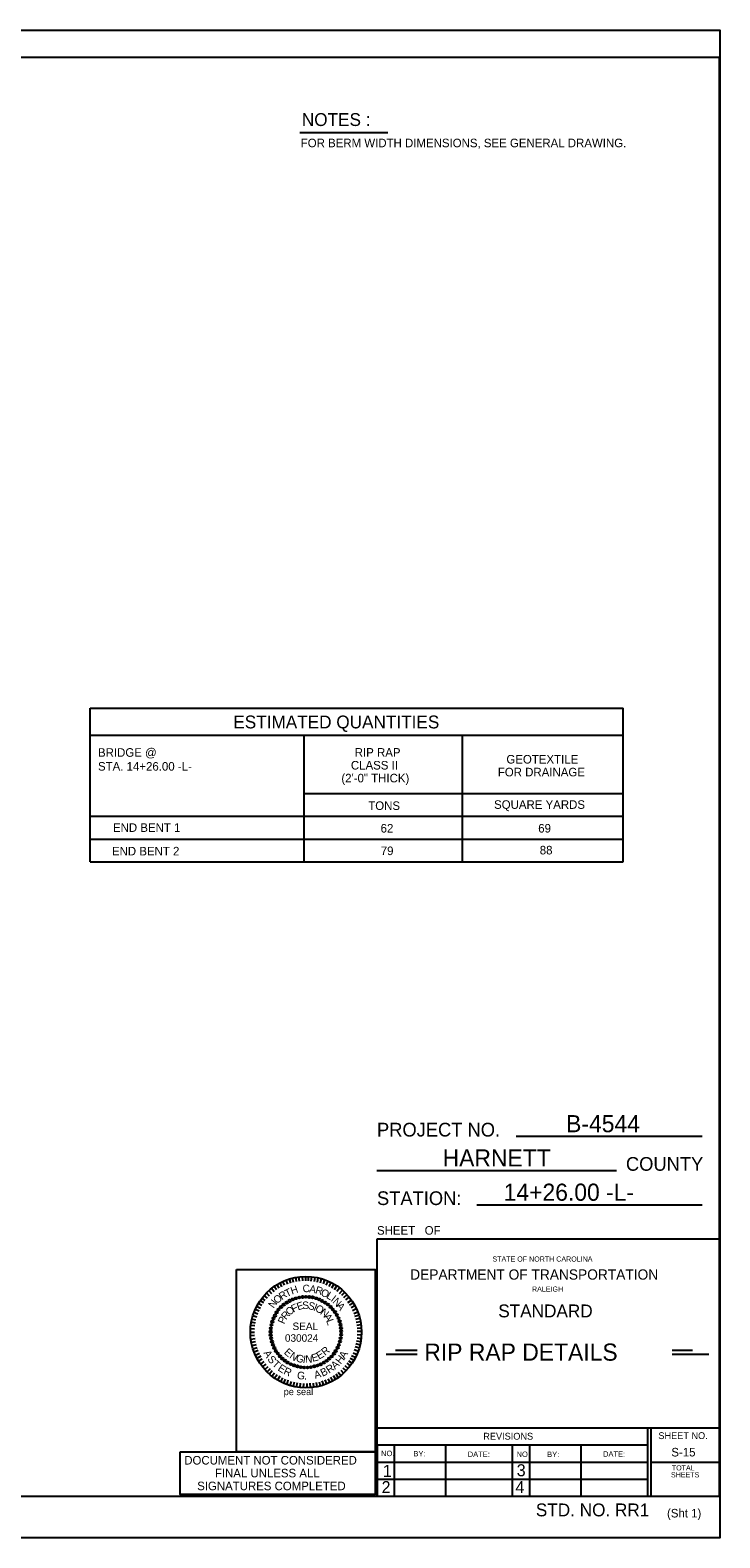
# Model space of a CAD drawing. Extents: x -102 to 265, y 0 to 198.
# Drawn here: x 183.9 to 264.5, y 0 to 176 of the extents above; entities that cross this region are included whole.
import ezdxf

# ---------------------------------------------------------------- set-up
doc = ezdxf.new("R2010")
doc.units = 0
for name, color, linetype in [('Peseal', 7, 'Continuous'), ('Plan Sheet', 7, 'Continuous'), ('Plan Sheet CELL', 7, 'Continuous'), ('Plot Shape', 7, 'Continuous'), ('Sheet Sticker Exception Certification CELL', 7, 'Continuous'), ('Text', 7, 'Continuous'), ('Title Text', 7, 'Continuous'), ('User Information Notes', 7, 'Continuous'), ('User Information Notes CELL', 7, 'Continuous')]:
    doc.layers.add(name, color=color, linetype=linetype)

msp = doc.modelspace()

# ---------------------------------------------------------------- linework, layer by layer
at = {"layer": 'Peseal'}
for p, q in [((214.01, 29.61), (213.82, 30.07)), ((214.36, 29.73), (214.2, 30.23)), ((214.7, 29.82), (214.57, 30.32)), ((215.04, 29.92), (214.95, 30.42)), ((215.39, 29.95), (215.32, 30.45)), ((215.76, 30.01), (215.73, 30.51)), ((216.14, 30.01), (216.14, 30.51)), ((216.42, 30.01), (216.45, 30.51)), ((216.76, 29.98), (216.82, 30.48)), ((217.14, 29.92), (217.2, 30.42)), ((217.48, 29.86), (217.57, 30.36)), ((217.82, 29.76), (217.95, 30.26)), ((218.17, 29.67), (218.36, 30.14)), ((218.51, 29.51), (218.73, 29.98)), ((211.64, 27.98), (211.26, 28.29)), ((211.89, 28.23), (211.51, 28.61)), ((212.14, 28.48), (211.82, 28.86)), ((212.42, 28.73), (212.11, 29.11)), ((212.7, 28.95), (212.42, 29.36)), ((213.01, 29.14), (212.76, 29.57)), ((213.32, 29.32), (213.11, 29.76)), ((213.64, 29.48), (213.45, 29.92)), ((218.86, 29.36), (219.07, 29.82)), ((219.17, 29.2), (219.42, 29.64)), ((219.48, 28.98), (219.76, 29.42)), ((219.76, 28.79), (220.07, 29.17)), ((220.07, 28.54), (220.39, 28.92)), ((220.32, 28.32), (220.67, 28.67)), ((220.57, 28.04), (220.95, 28.39)), ((210.67, 26.45), (210.2, 26.67)), ((210.82, 26.76), (210.36, 27.01)), ((210.98, 27.11), (210.54, 27.36)), ((211.2, 27.42), (210.76, 27.7)), ((211.39, 27.7), (211.01, 27.98)), ((220.79, 27.79), (221.2, 28.11)), ((221.04, 27.48), (221.45, 27.76)), ((221.23, 27.2), (221.64, 27.45)), ((221.42, 26.89), (221.86, 27.11)), ((221.57, 26.54), (222.01, 26.76)), ((210.17, 24.73), (209.7, 24.79)), ((210.23, 25.07), (209.73, 25.17)), ((210.29, 25.42), (209.82, 25.54)), ((210.39, 25.76), (209.92, 25.92)), ((210.51, 26.11), (210.04, 26.29)), ((221.73, 26.2), (222.2, 26.39)), ((221.86, 25.86), (222.32, 26.01)), ((221.95, 25.51), (222.42, 25.64)), ((222.01, 25.17), (222.51, 25.26)), ((222.07, 24.82), (222.57, 24.89)), ((210.14, 24.36), (209.64, 24.39)), ((210.14, 23.98), (209.64, 23.98)), ((210.14, 23.61), (209.64, 23.57)), ((210.2, 23.23), (209.7, 23.17)), ((210.23, 22.89), (209.76, 22.79)), ((222.04, 23.01), (222.54, 22.92)), ((222.11, 24.48), (222.61, 24.51)), ((222.11, 23.36), (222.61, 23.29)), ((222.14, 24.11), (222.64, 24.11)), ((222.14, 23.73), (222.64, 23.7)), ((210.32, 22.54), (209.82, 22.42)), ((210.42, 22.2), (209.95, 22.04)), ((210.54, 21.86), (210.07, 21.67)), ((210.7, 21.51), (210.23, 21.29)), ((210.86, 21.2), (210.39, 20.95)), ((221.48, 21.29), (221.95, 21.07)), ((221.64, 21.61), (222.11, 21.42)), ((221.79, 21.98), (222.26, 21.79)), ((221.89, 22.32), (222.39, 22.17)), ((221.98, 22.67), (222.48, 22.54)), ((211.04, 20.86), (210.61, 20.61)), ((211.23, 20.57), (210.82, 20.29)), ((211.45, 20.26), (211.04, 19.95)), ((211.67, 19.98), (211.32, 19.67)), ((211.95, 19.73), (211.57, 19.36)), ((212.2, 19.48), (211.89, 19.11)), ((220.2, 19.57), (220.51, 19.23)), ((220.45, 19.86), (220.82, 19.48)), ((220.7, 20.11), (221.07, 19.76)), ((220.92, 20.39), (221.32, 20.07)), ((221.11, 20.67), (221.54, 20.39)), ((221.32, 20.98), (221.76, 20.73)), ((212.48, 19.23), (212.2, 18.86)), ((212.76, 19.04), (212.48, 18.64)), ((213.07, 18.86), (212.82, 18.42)), ((213.39, 18.67), (213.17, 18.23)), ((213.7, 18.51), (213.51, 18.07)), ((214.04, 18.39), (213.89, 17.92)), ((214.42, 18.26), (214.26, 17.79)), ((214.76, 18.17), (214.64, 17.7)), ((215.11, 18.11), (215.01, 17.61)), ((215.48, 18.04), (215.42, 17.54)), ((215.86, 18.01), (215.82, 17.51)), ((216.23, 18.01), (216.23, 17.51)), ((216.61, 18.04), (216.64, 17.54)), ((216.98, 18.07), (217.04, 17.57)), ((217.32, 18.14), (217.42, 17.64)), ((217.67, 18.2), (217.79, 17.73)), ((218.01, 18.32), (218.17, 17.82)), ((218.36, 18.45), (218.54, 17.98)), ((218.7, 18.57), (218.92, 18.14)), ((219.01, 18.76), (219.26, 18.29)), ((219.32, 18.95), (219.61, 18.51)), ((219.64, 19.14), (219.92, 18.73)), ((219.92, 19.36), (220.23, 18.95))]:
    msp.add_line(p, q, dxfattribs=at)
for centre, radius in [((215.34, 28.06), 0.11), ((215.75, 28.11), 0.126), ((216.14, 28.14), 0.125), ((216.53, 28.11), 0.126), ((216.92, 28.07), 0.129), ((212.71, 26.31), 0.134), ((212.93, 26.65), 0.11), ((213.23, 26.95), 0.133), ((213.53, 27.21), 0.134), ((213.87, 27.46), 0.134), ((214.23, 27.67), 0.14), ((214.59, 27.84), 0.119), ((214.95, 27.96), 0.114), ((217.32, 27.96), 0.114), ((217.68, 27.84), 0.119), ((218.04, 27.65), 0.126), ((218.39, 27.46), 0.126), ((218.71, 27.23), 0.122), ((219.03, 26.95), 0.122), ((219.29, 26.65), 0.122), ((219.53, 26.36), 0.126), ((212.11, 24.86), 0.129), ((212.2, 25.25), 0.134), ((212.34, 25.62), 0.119), ((212.53, 25.95), 0.144), ((219.75, 26.01), 0.126), ((219.93, 25.65), 0.119), ((220.07, 25.28), 0.134), ((220.17, 24.89), 0.129), ((212.01, 24.07), 0.125), ((212.01, 23.68), 0.126), ((212.04, 24.46), 0.126), ((212.07, 23.28), 0.126), ((212.17, 22.89), 0.129), ((220.11, 22.92), 0.129), ((220.2, 23.31), 0.126), ((220.23, 24.5), 0.126), ((220.26, 24.11), 0.125), ((220.26, 23.71), 0.126), ((212.29, 22.53), 0.134), ((212.45, 22.17), 0.14), ((212.62, 21.82), 0.126), ((212.86, 21.53), 0.122), ((213.11, 21.2), 0.133), ((219.14, 21.18), 0.122), ((219.4, 21.5), 0.134), ((219.62, 21.82), 0.126), ((219.84, 22.2), 0.126), ((219.98, 22.53), 0.134), ((213.39, 20.92), 0.133), ((213.68, 20.68), 0.134), ((214.01, 20.46), 0.126), ((214.37, 20.28), 0.119), ((214.75, 20.14), 0.134), ((215.14, 20.01), 0.129), ((215.53, 19.92), 0.126), ((215.92, 19.89), 0.125), ((216.32, 19.89), 0.125), ((216.71, 19.92), 0.126), ((217.11, 20.01), 0.129), ((217.5, 20.12), 0.119), ((217.86, 20.26), 0.14), ((218.23, 20.46), 0.126), ((218.56, 20.67), 0.122), ((218.84, 20.92), 0.122)]:
    msp.add_circle(centre, radius, dxfattribs=at)
at = {"layer": 'Plan Sheet'}
for p, q in [((264.51, 176), (264.51, 176)), ((8.43, 172.85), (264.44, 172.85)), ((264.44, 172.85), (264.44, 4.85)), ((8.43, 4.85), (264.44, 4.85)), ((264.51, 0), (264.51, 0))]:
    msp.add_line(p, q, dxfattribs=at)
at = {"layer": 'Plan Sheet CELL'}
for p, q in [((262.44, 46.85), (240.7, 46.85)), ((252.44, 42.85), (224.44, 42.85)), ((262.44, 38.85), (236.12, 38.85)), ((264.44, 34.85), (224.44, 34.85)), ((224.44, 34.85), (224.44, 4.85)), ((224.44, 12.85), (264.44, 12.85)), ((256.04, 12.85), (256.04, 4.85)), ((256.44, 12.85), (256.44, 4.85)), ((224.44, 10.85), (256.05, 10.85)), ((224.46, 10.85), (224.46, 4.85)), ((226.43, 10.85), (226.43, 4.85)), ((232.43, 10.82), (232.43, 4.82)), ((240.24, 10.85), (240.24, 4.8)), ((242.25, 10.85), (242.25, 4.84)), ((248.25, 10.85), (248.25, 4.84)), ((224.44, 8.85), (256.12, 8.85)), ((256.44, 8.85), (264.37, 8.85)), ((224.44, 6.85), (256.05, 6.85))]:
    msp.add_line(p, q, dxfattribs=at)
at = {"layer": 'Plot Shape'}
msp.add_lwpolyline([(0, 176), (264.51, 176), (264.51, 0), (0, 0)], close=True, dxfattribs=at)
at = {"layer": 'Sheet Sticker Exception Certification CELL'}
msp.add_lwpolyline([(201.45, 10.06), (224.24, 10.06), (224.24, 5.05), (201.45, 5.05)], close=True, dxfattribs=at)
at = {"layer": 'Text'}
for p, q in [((215.43, 164.05), (225.69, 164.05)), ((190.91, 96.85), (253.22, 96.85)), ((190.91, 78.91), (190.91, 96.85)), ((253.22, 78.91), (253.22, 96.85)), ((190.91, 93.72), (253.22, 93.72)), ((215.93, 78.91), (215.93, 93.72)), ((234.42, 78.91), (234.42, 93.72)), ((215.93, 86.91), (253.22, 86.91)), ((190.91, 84.24), (253.22, 84.24)), ((190.91, 81.57), (253.22, 81.57)), ((190.91, 78.91), (253.22, 78.91)), ((225.51, 21.46), (229.12, 21.46)), ((226.6, 21.91), (229.12, 21.91)), ((258.94, 21.91), (261.29, 21.91)), ((258.94, 21.46), (263.21, 21.46))]:
    msp.add_line(p, q, dxfattribs=at)
at = {"layer": 'User Information Notes'}
msp.add_line((216.14, 24.01), (216.14, 24.01), dxfattribs=at)
at = {"layer": 'User Information Notes CELL'}
msp.add_line((216.14, 24.01), (216.14, 24.01), dxfattribs=at)
msp.add_lwpolyline([(208.04, 31.31), (224.24, 31.31), (224.24, 10.06), (208.04, 10.06)], close=True, dxfattribs=at)
msp.add_circle((216.14, 24.01), 6.5, dxfattribs=at)

# ---------------------------------------------------------------- texts
at = {"layer": 'Peseal'}
for s, height, rotation, p in [('O', 0.875, 39.9967, (212.76, 27.26)), ('R', 0.875, 32.9699, (213.32, 27.73)), ('T', 0.875, 25.943, (213.92, 28.07)), ('H', 0.875, 18.9162, (214.51, 28.39)), ('C', 0.875, 4.8625, (215.79, 28.64)), ('A', 0.875, 350.8088, (216.48, 28.67)), ('R', 0.875, 343.7819, (217.17, 28.57)), ('O', 0.875, 336.7551, (217.79, 28.32)), ('L', 0.875, 329.7282, (218.45, 28.04)), ('I', 0.875, 322.7014, (218.98, 27.7)), ('N', 0.875, 54.0504, (212.36, 26.73)), ('R', 0.875, 50.5765, (213.82, 25.39)), ('O', 0.875, 42.5436, (214.23, 25.89)), ('F', 0.875, 26.4777, (214.67, 26.29)), ('E', 0.875, 18.4448, (215.23, 26.54)), ('S', 0.875, 2.3789, (215.73, 26.7)), ('S', 0.875, 346.313, (216.32, 26.73)), ('I', 0.875, 338.28, (216.95, 26.57)), ('O', 0.875, 330.2471, (217.14, 26.54)), ('N', 0.875, 322.2141, (217.73, 26.17)), ('N', 0.875, 315.6745, (219.2, 27.51)), ('A', 0.875, 308.6477, (219.64, 27.04)), ('P', 0.875, 66.6424, (213.61, 24.89)), ('A', 0.875, 306.1483, (218.17, 25.79)), ('L', 0.875, 290.0824, (218.48, 25.36)), ('A', 0.887, 300.3993, (211.14, 21.59)), ('S', 0.887, 309.4349, (211.58, 20.83)), ('E', 0.875, 318.5179, (213.51, 21.57)), ('N', 0.875, 326.5361, (214.14, 21.04)), ('G', 0.875, 342.5725, (214.89, 20.64)), ('I', 0.875, 350.5906, (215.73, 20.45)), ('N', 0.875, 358.6088, (216.04, 20.45)), ('E', 0.875, 14.6452, (216.92, 20.54)), ('E', 0.875, 30.6815, (217.67, 20.79)), ('R', 0.875, 38.6997, (218.36, 21.23)), ('H', 0.887, 51.3597, (220.19, 20.21)), ('A', 0.887, 59.6007, (220.69, 20.83)), ('T', 0.887, 318.1096, (212.11, 20.18)), ('E', 0.887, 327.1453, (212.77, 19.6)), ('R', 0.888, 335.458, (213.44, 19.16)), ('G', 0.887, 353.3858, (215.06, 18.56)), ('A', 0.887, 15.7955, (217.22, 18.56)), ('B', 0.887, 24.8312, (218.07, 18.8)), ('R', 0.887, 33.5776, (218.84, 19.16)), ('A', 0.887, 42.3241, (219.54, 19.62)), ('.', 0.887, 2.1323, (215.91, 18.46))]:
    msp.add_text(s, height=height, rotation=rotation, dxfattribs=at).set_placement(p)
for s, p in [('SEAL', (214.57, 24.26)), ('030024', (213.68, 22.89))]:
    msp.add_text(s, height=0.875, dxfattribs=at).set_placement(p)
at = {"layer": 'Plan Sheet CELL'}
for s, height, p in [('PROJECT NO.', 1.6, (224.44, 46.85)), ('COUNTY', 1.6, (253.53, 42.85)), ('STATION:', 1.6, (224.44, 38.85)), ('SHEET   OF  ', 1, (224.44, 35.39)), ('STATE OF NORTH CAROLINA', 0.6, (237.93, 32.25)), ('DEPARTMENT OF TRANSPORTATION', 1.2, (228.32, 30.14)), ('RALEIGH', 0.6, (242.55, 28.74)), ('SHEET NO.', 0.8, (257.32, 11.53)), ('REVISIONS', 0.8, (236.86, 11.46)), ('NO.', 0.637, (224.91, 9.54)), ('BY:', 0.637, (228.69, 9.51)), ('DATE:', 0.637, (235.04, 9.44)), ('NO.', 0.637, (240.75, 9.44)), ('BY:', 0.637, (244.32, 9.43)), ('DATE:', 0.637, (250.85, 9.47)), ('1', 1.4, (225.12, 7.12)), ('3', 1.4, (240.77, 7.19)), ('SHEETS', 0.6, (258.79, 7.06)), ('TOTAL', 0.6, (258.89, 7.87)), ('2', 1.4, (224.98, 5.22)), ('4', 1.4, (240.62, 5.22))]:
    msp.add_text(s, height=height, dxfattribs=at).set_placement(p)
at = {"layer": 'Sheet Sticker Exception Certification CELL'}
for s, p in [('DOCUMENT NOT CONSIDERED', (201.92, 8.56)), ('FINAL UNLESS ALL', (205.5, 7.06)), ('SIGNATURES COMPLETED', (203.43, 5.56))]:
    msp.add_text(s, height=0.9978, dxfattribs=at).set_placement(p)
at = {"layer": 'Text'}
for s, height, p in [('NOTES :', 1.5, (215.66, 164.81)), ('FOR BERM WIDTH DIMENSIONS, SEE GENERAL DRAWING.', 1, (215.53, 162.33)), ('ESTIMATED QUANTITIES', 1.5, (207.65, 94.49)), ('BRIDGE @ ', 1, (191.84, 91.18)), ('RIP RAP', 1, (221.84, 91.19)), ('STA. 14+26.00 -L-', 0.9999, (191.84, 89.56)), ('CLASS II', 1, (221.39, 89.69)), ('FOR DRAINAGE', 0.9999, (238.56, 88.89)), ('GEOTEXTILE', 1, (239.56, 90.39)), ('(2\'-0" THICK)', 0.9999, (220.28, 88.19)), ('TONS', 1, (223.42, 84.97)), (' SQUARE YARDS', 0.9999, (237.75, 85.1)), ('END BENT 1', 1, (193.59, 82.41)), ('62', 1, (224.86, 82.33)), ('69', 1, (243.28, 82.33)), ('END BENT 2', 1, (193.47, 79.66)), ('79', 1, (224.88, 79.7)), ('88', 1, (243.46, 79.78)), ('STANDARD', 1.5, (238.61, 25.74)), ('RIP RAP DETAILS', 2, (229.97, 20.68)), ('S-15', 1, (258.83, 9.5)), ('STD. NO. RR1', 1.5, (243, 2.51)), ('(Sht 1)', 0.998, (258.33, 2.38))]:
    msp.add_text(s, height=height, dxfattribs=at).set_placement(p)
at = {"layer": 'Title Text'}
for s, p in [('B-4544', (246.54, 47.35)), ('HARNETT', (232.11, 43.35)), ('14+26.00 -L-', (239.24, 39.35))]:
    msp.add_text(s, height=2, dxfattribs=at).set_placement(p)
at = {"layer": 'User Information Notes CELL'}
msp.add_text('pe seal', height=0.8, dxfattribs=at).set_placement((213.54, 16.66))

doc.saveas('drawing.dxf')
